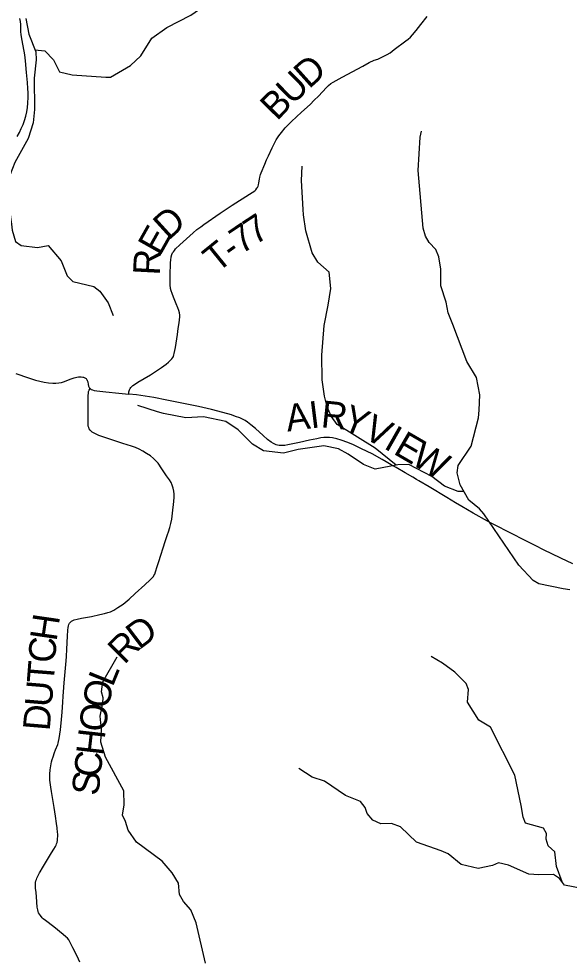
# Model space of a CAD drawing. Extents: x 0 to 34, y 0 to 22.
# Drawn here: x 6.364 to 7.525, y 16.31 to 18.295 of the extents above; entities that cross this region are included whole.
import ezdxf

# ---------------------------------------------------------------- set-up
doc = ezdxf.new("R2010")
doc.units = 0
for name, color, linetype in [('GM_X_County_Road', 7, 'Continuous'), ('GM_X_Minor_River', 7, 'Continuous'), ('GM_X_Township_Road', 7, 'Continuous'), ('GM_X_Township_Road_Text', 7, 'Continuous')]:
    doc.layers.add(name, color=color, linetype=linetype)

msp = doc.modelspace()

# ---------------------------------------------------------------- linework, layer by layer
at = {"layer": 'GM_X_County_Road'}
msp.add_lwpolyline([(6.3604, 18.0473), (6.3648, 18.0555), (6.3689, 18.0639), (6.3727, 18.0723), (6.3759, 18.081), (6.3784, 18.0899), (6.3804, 18.099), (6.3818, 18.1081), (6.3827, 18.1173), (6.3832, 18.1298), (6.3832, 18.1394), (6.3828, 18.1485), (6.3819, 18.1609), (6.38, 18.1822), (6.3774, 18.2068), (6.376, 18.2191), (6.3727, 18.2383), (6.3698, 18.2527), (6.3685, 18.2619), (6.3679, 18.2681), (6.3678, 18.2743), (6.3677, 18.2835), (6.3671, 18.2897), (6.3661, 18.2957)], dxfattribs=at)
at = {"layer": 'GM_X_Minor_River'}
for points in [[(6.3977, 18.2296), (6.4186, 18.2279), (6.4369, 18.2086), (6.4495, 18.1836), (6.4761, 18.1773), (6.547, 18.1723), (6.5572, 18.1724), (6.5992, 18.1968), (6.6211, 18.217), (6.644, 18.2543), (6.6758, 18.2768), (6.7268, 18.3032), (6.7793, 18.3399), (6.8243, 18.3659), (6.8701, 18.374), (6.9066, 18.3628), (6.9191, 18.3613), (6.9551, 18.3638), (7.0213, 18.3846), (7.0444, 18.396), (7.0804, 18.403), (7.105, 18.4039), (7.1512, 18.4086)], [(6.3781, 18.296), (6.3851, 18.2627), (6.3993, 18.2255), (6.4005, 18.2085), (6.3962, 18.1698), (6.3968, 18.1038), (6.3936, 18.0757), (6.3835, 18.043), (6.3553, 17.9924), (6.3456, 17.9666), (6.3413, 17.9127), (6.3479, 17.8619), (6.3499, 17.8497), (6.3564, 17.8255), (6.3686, 17.8172), (6.4031, 17.8132), (6.4258, 17.8175), (6.4533, 17.7846), (6.4659, 17.7531), (6.4774, 17.7414), (6.5221, 17.7306), (6.5347, 17.7212), (6.5519, 17.6962), (6.563, 17.6697)], [(7.5257, 17.0913), (7.512, 17.0931), (7.4608, 17.1035), (7.4483, 17.111), (7.4186, 17.1428), (7.3449, 17.2517), (7.3354, 17.2619), (7.3126, 17.2804), (7.2946, 17.3122), (7.2881, 17.3379), (7.2906, 17.3531), (7.3177, 17.3942), (7.333, 17.4538), (7.3344, 17.4702), (7.3362, 17.502), (7.3292, 17.5388), (7.309, 17.5729), (7.2794, 17.6509), (7.2691, 17.6755), (7.2652, 17.6975), (7.2536, 17.7323), (7.2539, 17.7676), (7.2496, 17.7934), (7.2434, 17.8085), (7.229, 17.8233), (7.2217, 17.8369), (7.2167, 17.8539), (7.2059, 17.9757), (7.2101, 18.0459), (7.2131, 18.058)], [(7.1598, 17.3538), (7.1154, 17.3899), (7.0355, 17.44), (7.0222, 17.4574), (7.0138, 17.4767), (7.0087, 17.4998), (7.0036, 17.5343), (7.003, 17.5859), (7.0081, 17.6485), (7.0162, 17.6914), (7.0217, 17.7264), (7.0185, 17.7612), (6.9945, 17.7824), (6.9827, 17.8017), (6.9692, 17.8483), (6.9645, 17.882), (6.9637, 17.8934), (6.96, 17.9541), (6.9614, 17.9848)], [(7.3023, 17.2986), (7.2905, 17.2985), (7.2613, 17.3094), (7.2347, 17.3301), (7.1864, 17.3557), (7.1633, 17.3544), (7.1156, 17.3459), (7.0909, 17.3553), (7.0582, 17.3775), (7.0377, 17.3884), (7.0073, 17.3947), (6.9532, 17.3869), (6.9221, 17.3792), (6.88, 17.3839), (6.8565, 17.3986), (6.8264, 17.4284), (6.8001, 17.4458), (6.7535, 17.4562), (6.716, 17.4538), (6.6685, 17.463), (6.6564, 17.4664), (6.615, 17.4795)], [(6.7573, 16.3041), (6.7379, 16.389), (6.7264, 16.4162), (6.7108, 16.4336), (6.7024, 16.4488), (6.7008, 16.4727), (6.6874, 16.4946), (6.6661, 16.5188), (6.6117, 16.5588), (6.5941, 16.5845), (6.5887, 16.6027), (6.5822, 16.6159), (6.5859, 16.6376), (6.5854, 16.6675), (6.5464, 16.7383), (6.5368, 16.7697), (6.5378, 16.7967), (6.5354, 16.8247), (6.5406, 16.8528), (6.5413, 16.8635), (6.5378, 16.876), (6.5408, 16.8968), (6.5712, 16.9497)], [(7.5096, 16.4752), (7.4981, 16.5077), (7.4941, 16.5384), (7.4801, 16.5512), (7.4758, 16.5652), (7.4769, 16.5774), (7.4704, 16.5884), (7.4328, 16.5988), (7.4275, 16.6117), (7.4232, 16.6367), (7.41, 16.7004), (7.3588, 16.8014), (7.3341, 16.8161), (7.31, 16.854), (7.3125, 16.8813), (7.3075, 16.8938), (7.2836, 16.9176), (7.2577, 16.9368), (7.2334, 16.9504)], [(7.5514, 16.4616), (7.5149, 16.4687), (7.5039, 16.4823), (7.4913, 16.4906), (7.4606, 16.4901), (7.4394, 16.4915), (7.3969, 16.5106), (7.3752, 16.5155), (7.3631, 16.5097), (7.3325, 16.5035), (7.2968, 16.5117), (7.269, 16.5347), (7.2546, 16.5411), (7.2022, 16.5591), (7.1691, 16.5912), (7.1497, 16.5983), (7.1274, 16.5978), (7.1107, 16.6057), (7.0985, 16.6197), (7.0942, 16.6322), (7.0843, 16.6451), (7.0528, 16.6571), (7.0083, 16.6876), (6.9821, 16.6958), (6.9544, 16.7147)]]:
    msp.add_lwpolyline(points, dxfattribs=at)
at = {"layer": 'GM_X_Township_Road'}
for points in [[(6.5956, 17.504), (6.596, 17.5087), (6.5962, 17.5106), (6.5968, 17.5131), (6.5983, 17.5157), (6.6001, 17.518), (6.6022, 17.5201), (6.6045, 17.5221), (6.6095, 17.5257), (6.6147, 17.529), (6.6412, 17.5444), (6.6543, 17.5526), (6.6645, 17.5597), (6.6744, 17.5673), (6.6792, 17.5714), (6.6819, 17.5737), (6.6844, 17.576), (6.6864, 17.5785), (6.6882, 17.5808), (6.6897, 17.5835), (6.6908, 17.5864), (6.6916, 17.5896), (6.6928, 17.5959), (6.6941, 17.602), (6.6955, 17.6112), (6.6967, 17.6205), (6.6981, 17.6297), (6.6999, 17.6419), (6.7022, 17.6542), (6.7028, 17.6604), (6.7034, 17.6667), (6.7033, 17.6706), (6.7027, 17.6752), (6.7012, 17.6802), (6.6992, 17.686), (6.6958, 17.694), (6.6899, 17.7083), (6.6868, 17.7162), (6.685, 17.7217), (6.6838, 17.7263), (6.6829, 17.7341), (6.6826, 17.7443), (6.6828, 17.7504), (6.6829, 17.7598), (6.6833, 17.7753), (6.6837, 17.7814), (6.684, 17.7865), (6.6848, 17.7931), (6.6863, 17.7982), (6.6881, 17.8015), (6.6898, 17.8041), (6.6918, 17.8068), (6.6945, 17.8103), (6.703, 17.8183), (6.7311, 17.8437), (6.7395, 17.8509), (6.7473, 17.8567), (6.7539, 17.8613), (6.7886, 17.8856), (6.8136, 17.902), (6.8504, 17.9255), (6.8558, 17.9289), (6.8612, 17.9326), (6.8633, 17.9346), (6.8659, 17.9378), (6.8672, 17.9398), (6.8679, 17.9413), (6.8684, 17.9425), (6.869, 17.9448), (6.8701, 17.9492), (6.8715, 17.9572), (6.8721, 17.9616), (6.8735, 17.9669), (6.8746, 17.9705), (6.8823, 17.9889), (6.8863, 17.9976), (6.89, 18.0063), (6.8979, 18.023), (6.902, 18.0315), (6.9067, 18.0402), (6.9123, 18.0483), (6.9177, 18.0557), (6.9256, 18.0653), (6.9391, 18.079), (6.9599, 18.0986), (6.9779, 18.1148), (6.9868, 18.1235), (6.9956, 18.1323), (7.0041, 18.1414), (7.0125, 18.1505), (7.0168, 18.1547), (7.0216, 18.1585), (7.0268, 18.1617), (7.0456, 18.1723), (7.0891, 18.1956), (7.1027, 18.2031), (7.1134, 18.2077), (7.1208, 18.2104), (7.1278, 18.2137), (7.1352, 18.2173), (7.1406, 18.2201), (7.1468, 18.2238), (7.1512, 18.2269), (7.1555, 18.2304), (7.1801, 18.2485), (7.185, 18.2525), (7.1896, 18.2567), (7.194, 18.2613), (7.2019, 18.2709), (7.2114, 18.2832), (7.2249, 18.3002)], [(6.3577, 17.5475), (6.3841, 17.5381), (6.3988, 17.5333), (6.4079, 17.531), (6.417, 17.5291), (6.4262, 17.5278), (6.4355, 17.5269), (6.4417, 17.5269), (6.4479, 17.5274), (6.4539, 17.5285), (6.4599, 17.5303), (6.4685, 17.5338), (6.4742, 17.5363), (6.4801, 17.5383), (6.4861, 17.5397), (6.4892, 17.5402), (6.4923, 17.5405), (6.4954, 17.5404), (6.4984, 17.5399), (6.4999, 17.5396), (6.5014, 17.539), (6.5042, 17.5376), (6.5054, 17.5367), (6.5065, 17.5356), (6.5074, 17.5344), (6.5081, 17.5329), (6.509, 17.53), (6.51, 17.5238), (6.5107, 17.5208), (6.5113, 17.5194), (6.5121, 17.518), (6.5129, 17.5168), (6.5141, 17.5157)], [(6.4921, 16.3063), (6.4869, 16.3184), (6.4777, 16.336), (6.4718, 16.3475), (6.4689, 16.3531), (6.4661, 16.3567), (6.4629, 16.3597), (6.4571, 16.3646), (6.4372, 16.3804), (6.42, 16.3936), (6.4152, 16.3976), (6.4131, 16.3998), (6.4091, 16.4046), (6.4074, 16.4069), (6.4055, 16.4098), (6.4045, 16.4128), (6.4036, 16.4167), (6.4027, 16.4217), (6.4008, 16.4435), (6.3999, 16.4528), (6.3989, 16.462), (6.3986, 16.4682), (6.3987, 16.4713), (6.399, 16.4743), (6.3997, 16.4773), (6.4006, 16.4802), (6.4018, 16.4831), (6.4029, 16.486), (6.4042, 16.4888), (6.4073, 16.4941), (6.4089, 16.4968), (6.4135, 16.5048), (6.4262, 16.526), (6.4327, 16.5365), (6.4377, 16.5443), (6.4409, 16.5497), (6.4422, 16.5525), (6.4433, 16.5554), (6.4442, 16.5583), (6.4453, 16.5631), (6.4455, 16.5675), (6.4458, 16.5706), (6.4457, 16.5766), (6.4453, 16.5797), (6.4442, 16.589), (6.443, 16.5982), (6.4408, 16.6136), (6.4379, 16.6319), (6.4345, 16.6533), (6.4325, 16.6656), (6.431, 16.6747), (6.4294, 16.6899), (6.4289, 16.6951), (6.4289, 16.7027), (6.4299, 16.7119), (6.431, 16.7203), (6.4326, 16.7286), (6.4341, 16.7337), (6.4358, 16.7392), (6.439, 16.748), (6.4412, 16.7538), (6.4456, 16.7653), (6.4465, 16.7681), (6.4473, 16.7714), (6.4486, 16.7774), (6.4502, 16.7866), (6.4514, 16.7958), (6.4535, 16.8175), (6.4549, 16.8329), (6.4566, 16.8546), (6.4574, 16.867), (6.4578, 16.8763), (6.4591, 16.8948), (6.4605, 16.9103), (6.4632, 16.9412), (6.464, 16.9504), (6.4651, 16.9658), (6.4661, 16.9936), (6.4668, 17.0059), (6.4676, 17.012), (6.4683, 17.015), (6.4694, 17.0178), (6.4708, 17.0205), (6.4727, 17.023), (6.475, 17.025), (6.4776, 17.0266), (6.4804, 17.0279), (6.4866, 17.0294), (6.4957, 17.0312), (6.5168, 17.0352), (6.5348, 17.0389), (6.5442, 17.041), (6.5516, 17.0431), (6.5568, 17.0449), (6.56, 17.0462), (6.564, 17.0484), (6.5728, 17.0536), (6.5837, 17.061), (6.5961, 17.0712), (6.6088, 17.0834), (6.6298, 17.1018), (6.6407, 17.1121), (6.6443, 17.1156), (6.6476, 17.1193), (6.6488, 17.1211), (6.6504, 17.124), (6.6521, 17.129), (6.6554, 17.14), (6.659, 17.1509), (6.6721, 17.1931), (6.6774, 17.2076), (6.6794, 17.2135), (6.6822, 17.2224), (6.6845, 17.2313), (6.6864, 17.2404), (6.6881, 17.2526), (6.6906, 17.2772), (6.6911, 17.2864), (6.691, 17.2926), (6.6907, 17.2991), (6.6895, 17.3053), (6.6873, 17.3119), (6.6847, 17.3174), (6.6812, 17.3234), (6.6755, 17.3317), (6.6654, 17.3465), (6.6577, 17.3579), (6.6528, 17.3635), (6.6475, 17.3681), (6.6414, 17.3734), (6.6333, 17.3789), (6.6256, 17.3832), (6.6172, 17.3881), (6.6096, 17.3911), (6.6016, 17.3938), (6.583, 17.3999), (6.562, 17.407), (6.5411, 17.414), (6.5322, 17.4169), (6.5265, 17.4193), (6.521, 17.4221), (6.5184, 17.4238), (6.516, 17.4259), (6.5139, 17.4281), (6.5122, 17.4307), (6.511, 17.4335), (6.5102, 17.4365), (6.5098, 17.4396), (6.5096, 17.4458), (6.5098, 17.4613), (6.5099, 17.4892), (6.5102, 17.5017), (6.5103, 17.5049), (6.5105, 17.507), (6.5109, 17.5091), (6.5122, 17.5124), (6.5141, 17.5157)], [(6.5141, 17.5157), (6.5151, 17.5148), (6.5165, 17.5139), (6.5194, 17.5127), (6.5223, 17.5118), (6.5284, 17.5106), (6.5469, 17.5084), (6.5748, 17.5058), (6.5956, 17.504)], [(7.5321, 17.1457), (7.5069, 17.1579), (7.4707, 17.1755), (7.454, 17.1838), (7.4291, 17.1964), (7.4044, 17.2093), (7.3934, 17.2151), (7.374, 17.2248), (7.3602, 17.2317), (7.352, 17.2361), (7.3224, 17.2528), (7.2983, 17.2669), (7.285, 17.2748), (7.2664, 17.2859), (7.2557, 17.2922), (7.2397, 17.3017), (7.2291, 17.308), (7.2078, 17.3207), (7.2025, 17.3239), (7.1945, 17.3285), (7.1785, 17.3379), (7.1597, 17.3488), (7.1489, 17.355), (7.1382, 17.3612), (7.1303, 17.3661), (7.1087, 17.3781), (7.0863, 17.3888), (7.0694, 17.3967), (7.058, 17.4015), (7.0434, 17.4067), (7.0345, 17.4094), (7.0254, 17.4116), (7.0193, 17.4125), (7.0133, 17.4127), (7.007, 17.4124), (7.0005, 17.4115), (6.992, 17.4097), (6.9767, 17.4068), (6.9556, 17.4018), (6.9311, 17.3969), (6.925, 17.3958), (6.9188, 17.3953), (6.9157, 17.3954), (6.9126, 17.3957), (6.9096, 17.3962), (6.9066, 17.397), (6.9037, 17.3981), (6.9009, 17.3994), (6.8957, 17.4028), (6.8883, 17.4084), (6.8789, 17.4164), (6.8628, 17.4311), (6.8534, 17.4392), (6.846, 17.4449), (6.8408, 17.4482), (6.8353, 17.4511), (6.8297, 17.4536), (6.821, 17.4569), (6.8121, 17.4598), (6.7942, 17.4649), (6.7702, 17.4711), (6.743, 17.4774), (6.7217, 17.4819), (6.6761, 17.4909), (6.6488, 17.4965), (6.6305, 17.4998), (6.6121, 17.5024), (6.5956, 17.504)]]:
    msp.add_lwpolyline(points, dxfattribs=at)

# ---------------------------------------------------------------- texts
at = {"layer": 'GM_X_Township_Road_Text'}
for s, rotation, p in [('D', 41.8792, (6.9757, 18.1461)), ('U', 44.3972, (6.9405, 18.1116)), ('B', 45.4029, (6.9079, 18.0785)), ('D', 42.3227, (6.6795, 17.8267)), ('7', 33.1214, (6.8617, 17.817)), ('7', 33.9253, (6.8329, 17.7975)), ('E', 60.624, (6.6616, 17.7934)), ('T', 38.9583, (6.7819, 17.7581)), ('-', 35.3271, (6.8141, 17.7843)), ('R', 87.0442, (6.6611, 17.7534)), ('I', 7.0747, (6.9798, 17.4313)), ('R', 354.1038, (6.9996, 17.4342)), ('A', 7.6912, (6.9304, 17.4247)), ('Y', 338.5767, (7.042, 17.4303)), ('V', 333.3649, (7.0873, 17.4126)), ('I', 330.4313, (7.1313, 17.3906)), ('E', 329.8543, (7.1515, 17.3792)), ('W', 329.8111, (7.1882, 17.3578)), ('H', 81.7277, (6.4431, 16.9813)), ('D', 37.1242, (6.6175, 16.9635)), ('R', 44.7626, (6.5859, 16.9319)), ('C', 86.5715, (6.4404, 16.936)), ('T', 85.4583, (6.437, 16.8924)), ('L', 67.9877, (6.5615, 16.8846)), ('U', 85.2382, (6.4328, 16.8424)), ('O', 78.7708, (6.5526, 16.8383)), ('D', 85.237, (6.4287, 16.7925)), ('O', 82.7534, (6.5465, 16.7897)), ('H', 83.513, (6.5408, 16.7402)), ('C', 83.542, (6.5356, 16.6938)), ('S', 83.5386, (6.5313, 16.6557))]:
    msp.add_text(s, height=0.0568, rotation=rotation, dxfattribs=at).set_placement(p)

doc.saveas('drawing.dxf')
